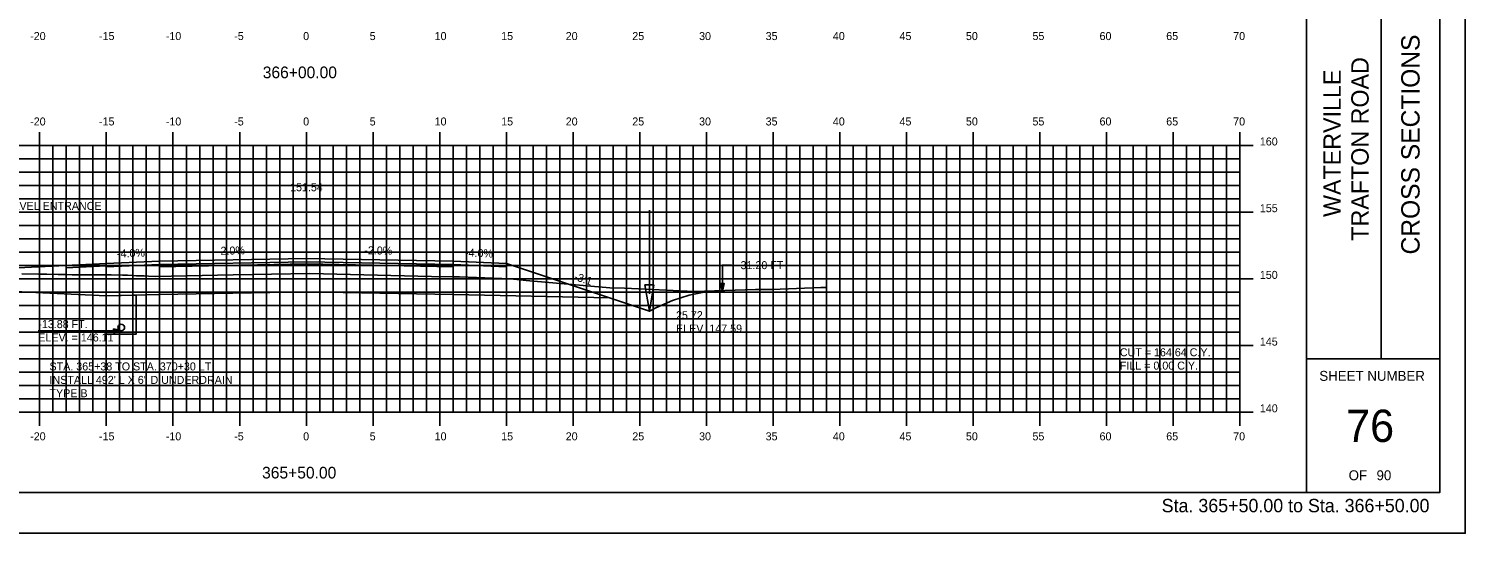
# Model space of a CAD drawing. Extents: x 1147412 to 1147582, y 608981 to 609091.
# Drawn here: x 1147473.9 to 1147581.6, y 608981.3 to 609019.1 of the extents above; entities that cross this region are included whole.
import ezdxf

# ---------------------------------------------------------------- set-up
doc = ezdxf.new("R2010")
doc.units = 0
for name, color, linetype in [('ANNOTATION', 7, 'Continuous'), ('BORDER', 7, 'Continuous'), ('D_Drainage_Ditch_Line', 7, 'Continuous'), ('D_Drainage_Underdrain', 7, 'Continuous'), ('D_Drainage_Underdrain_06in', 7, 'Continuous'), ('D_Roadway_Centerline', 7, 'Continuous'), ('D_Roadway_Centerline_Text', 7, 'Continuous'), ('D_Roadway_Edge_Shoulder', 7, 'Continuous'), ('D_Roadway_Edge_TW', 7, 'Continuous'), ('D_Roadway_Pavement', 7, 'Continuous'), ('D_Roadway_SlopeLines', 7, 'Continuous'), ('D_Roadway_SubGrade', 7, 'Continuous'), ('D_Text_Standard', 7, 'Continuous'), ('H_V ANNOTATION', 7, 'Continuous'), ('HIGHWAY_TITLE', 7, 'Continuous'), ('MAJOR', 7, 'Continuous'), ('MINOR', 7, 'Continuous'), ('PLOT BOUNDARY', 7, 'Continuous'), ('S_Roadway_Centerline', 7, 'Continuous')]:
    doc.layers.add(name, color=color, linetype=linetype)

msp = doc.modelspace()

# ---------------------------------------------------------------- linework, layer by layer
msp.add_lwpolyline([(1147464.92, 609000.76), (1147479.7, 609001.5), (1147483.7, 609001.66), (1147494.7, 609001.88), (1147505.7, 609001.66), (1147509.7, 609001.5), (1147517.42, 608998.92), (1147520.42, 608997.92), (1147520.9, 608998.16), (1147522.15, 608998.71), (1147523.4, 608999.11), (1147524.65, 608999.36), (1147525.9, 608999.46)])
at = {"layer": 'BORDER'}
for p, q in [((1147569.7, 608984.34), (1147569.7, 609089.34)), ((1147575.29, 608994.34), (1147575.29, 609029.34)), ((1147569.7, 608994.34), (1147579.7, 608994.34))]:
    msp.add_line(p, q, dxfattribs=at)
msp.add_lwpolyline([(1147419.7, 608984.34), (1147579.7, 608984.34), (1147579.7, 609089.34), (1147419.7, 609089.34)], close=True, dxfattribs=at)
at = {"layer": 'D_Drainage_Ditch_Line'}
msp.add_line((1147520.42, 608999.23), (1147520.42, 609005.48), dxfattribs=at)
msp.add_lwpolyline([(1147520.09, 608999.89), (1147520.75, 608999.89), (1147520.42, 608997.92)], close=True, dxfattribs=at)
at = {"layer": 'D_Drainage_Underdrain'}
msp.add_lwpolyline([(1147479.7, 608999.08), (1147479.7, 608996.2), (1147481.95, 608996.2), (1147481.95, 608999.12)], close=True, dxfattribs=at)
at = {"layer": 'D_Drainage_Underdrain_06in'}
msp.add_lwpolyline([(1147480.82, 608996.95), (1147480.9, 608996.93), (1147480.97, 608996.9), (1147481.02, 608996.84), (1147481.06, 608996.77), (1147481.07, 608996.7), (1147481.06, 608996.62), (1147481.02, 608996.55), (1147480.97, 608996.49), (1147480.9, 608996.46), (1147480.82, 608996.45), (1147480.75, 608996.46), (1147480.68, 608996.49), (1147480.62, 608996.55), (1147480.58, 608996.62), (1147480.57, 608996.7), (1147480.58, 608996.77), (1147480.62, 608996.84), (1147480.68, 608996.9), (1147480.75, 608996.93)], close=True, dxfattribs=at)
at = {"layer": 'D_Roadway_Edge_Shoulder'}
for points in [[(1147479.7, 609001.5), (1147476.7, 609001.35), (1147476.7, 609001.18), (1147479.7, 609001.33)], [(1147483.7, 609001.66), (1147479.7, 609001.5), (1147479.7, 609001.25), (1147483.7, 609001.41)], [(1147505.7, 609001.66), (1147509.7, 609001.5), (1147509.7, 609001.25), (1147505.7, 609001.41)]]:
    msp.add_lwpolyline(points, close=True, dxfattribs=at)
at = {"layer": 'D_Roadway_Edge_TW'}
msp.add_lwpolyline([(1147483.7, 609001.41), (1147483.7, 609001.66), (1147494.7, 609001.88), (1147505.7, 609001.66), (1147505.7, 609001.41), (1147494.7, 609001.63)], close=True, dxfattribs=at)
at = {"layer": 'D_Roadway_Pavement'}
msp.add_lwpolyline([(1147483.7, 609001.24), (1147483.7, 609001.41), (1147494.7, 609001.63), (1147505.7, 609001.41), (1147505.7, 609001.24), (1147494.7, 609001.46)], close=True, dxfattribs=at)
at = {"layer": 'D_Roadway_SlopeLines'}
for points in [[(1147520.42, 608997.92), (1147520.9, 608998.16), (1147522.15, 608998.71), (1147523.4, 608999.11), (1147524.65, 608999.36), (1147525.9, 608999.46)], [(1147517.42, 608998.92), (1147520.42, 608997.92)]]:
    msp.add_lwpolyline(points, dxfattribs=at)
at = {"layer": 'D_Roadway_SubGrade'}
for points in [[(1147464.92, 608999.76), (1147479.7, 608999.08), (1147483.7, 608999.16), (1147483.7, 609001.24), (1147483.7, 609001.41), (1147479.7, 609001.25), (1147479.7, 609001.5), (1147464.92, 609000.76)], [(1147483.7, 608999.16), (1147483.7, 609001.24), (1147494.7, 609001.46), (1147505.7, 609001.24), (1147505.7, 608999.16), (1147494.7, 608999.38)], [(1147505.7, 609001.24), (1147505.7, 609001.41), (1147509.7, 609001.25), (1147509.7, 609001.5), (1147509.7, 609001.5), (1147517.42, 608998.92), (1147505.7, 608999.16)]]:
    msp.add_lwpolyline(points, close=True, dxfattribs=at)
at = {"layer": 'D_Text_Standard'}
msp.add_line((1147474.6, 608996.45), (1147479.02, 608996.45), dxfattribs=at)
for points in [[(1147525.9, 608999.41), (1147525.9, 609001.37), (1147526.58, 609001.37)], [(1147480.82, 608996.45), (1147479.7, 608996.45), (1147479.02, 608996.45)]]:
    msp.add_lwpolyline(points, dxfattribs=at)
for points in [[(1147525.9, 608999.41), (1147525.75, 608999.99), (1147526.04, 608999.99)], [(1147480.82, 608996.45), (1147480.24, 608996.3), (1147480.24, 608996.59)]]:
    msp.add_lwpolyline(points, close=True, dxfattribs=at)
at = {"layer": 'MAJOR'}
for p, q in [((1147474.7, 609011.34), (1147474.7, 609010.34)), ((1147479.7, 609011.34), (1147479.7, 609010.34)), ((1147484.7, 609011.34), (1147484.7, 609010.34)), ((1147489.7, 609011.34), (1147489.7, 609010.34)), ((1147494.7, 609011.34), (1147494.7, 609010.34)), ((1147499.7, 609011.34), (1147499.7, 609010.34)), ((1147504.7, 609011.34), (1147504.7, 609010.34)), ((1147509.7, 609011.34), (1147509.7, 609010.34)), ((1147514.7, 609011.34), (1147514.7, 609010.34)), ((1147519.7, 609011.34), (1147519.7, 609010.34)), ((1147524.7, 609011.34), (1147524.7, 609010.34)), ((1147529.7, 609011.34), (1147529.7, 609010.34)), ((1147534.7, 609011.34), (1147534.7, 609010.34)), ((1147539.7, 609011.34), (1147539.7, 609010.34)), ((1147544.7, 609011.34), (1147544.7, 609010.34)), ((1147549.7, 609011.34), (1147549.7, 609010.34)), ((1147554.7, 609011.34), (1147554.7, 609010.34)), ((1147559.7, 609011.34), (1147559.7, 609010.34)), ((1147564.7, 609011.34), (1147564.7, 609010.34)), ((1147424.7, 609010.34), (1147564.7, 609010.34)), ((1147424.7, 609010.34), (1147564.7, 609010.34)), ((1147474.7, 608990.34), (1147474.7, 609010.34)), ((1147479.7, 608990.34), (1147479.7, 609010.34)), ((1147484.7, 608990.34), (1147484.7, 609010.34)), ((1147489.7, 608990.34), (1147489.7, 609010.34)), ((1147494.7, 608990.34), (1147494.7, 609010.34)), ((1147499.7, 608990.34), (1147499.7, 609010.34)), ((1147504.7, 608990.34), (1147504.7, 609010.34)), ((1147509.7, 608990.34), (1147509.7, 609010.34)), ((1147514.7, 608990.34), (1147514.7, 609010.34)), ((1147519.7, 608990.34), (1147519.7, 609010.34)), ((1147524.7, 608990.34), (1147524.7, 609010.34)), ((1147529.7, 608990.34), (1147529.7, 609010.34)), ((1147534.7, 608990.34), (1147534.7, 609010.34)), ((1147539.7, 608990.34), (1147539.7, 609010.34)), ((1147544.7, 608990.34), (1147544.7, 609010.34)), ((1147549.7, 608990.34), (1147549.7, 609010.34)), ((1147554.7, 608990.34), (1147554.7, 609010.34)), ((1147559.7, 608990.34), (1147559.7, 609010.34)), ((1147565.7, 609010.34), (1147563.7, 609010.34)), ((1147564.7, 608990.34), (1147564.7, 609010.34)), ((1147564.7, 608990.34), (1147564.7, 609010.34)), ((1147424.7, 609005.34), (1147564.7, 609005.34)), ((1147565.7, 609005.34), (1147563.7, 609005.34)), ((1147424.7, 609000.34), (1147564.7, 609000.34)), ((1147565.7, 609000.34), (1147563.7, 609000.34)), ((1147424.7, 608995.34), (1147564.7, 608995.34)), ((1147565.7, 608995.34), (1147563.7, 608995.34)), ((1147424.7, 608990.34), (1147564.7, 608990.34)), ((1147424.7, 608990.34), (1147564.7, 608990.34)), ((1147474.7, 608989.33), (1147474.7, 608990.34)), ((1147479.7, 608989.33), (1147479.7, 608990.34)), ((1147484.7, 608989.33), (1147484.7, 608990.34)), ((1147489.7, 608989.33), (1147489.7, 608990.34)), ((1147494.7, 608989.33), (1147494.7, 608990.34)), ((1147499.7, 608989.33), (1147499.7, 608990.34)), ((1147504.7, 608989.33), (1147504.7, 608990.34)), ((1147509.7, 608989.33), (1147509.7, 608990.34)), ((1147514.7, 608989.33), (1147514.7, 608990.34)), ((1147519.7, 608989.33), (1147519.7, 608990.34)), ((1147524.7, 608989.33), (1147524.7, 608990.34)), ((1147529.7, 608989.33), (1147529.7, 608990.34)), ((1147534.7, 608989.33), (1147534.7, 608990.34)), ((1147539.7, 608989.33), (1147539.7, 608990.34)), ((1147544.7, 608989.33), (1147544.7, 608990.34)), ((1147549.7, 608989.33), (1147549.7, 608990.34)), ((1147554.7, 608989.33), (1147554.7, 608990.34)), ((1147559.7, 608989.33), (1147559.7, 608990.34)), ((1147565.7, 608990.34), (1147563.7, 608990.34)), ((1147564.7, 608989.33), (1147564.7, 608990.34))]:
    msp.add_line(p, q, dxfattribs=at)
at = {"layer": 'MINOR'}
for p, q in [((1147475.7, 608990.34), (1147475.7, 609010.34)), ((1147476.7, 608990.34), (1147476.7, 609010.34)), ((1147477.7, 608990.34), (1147477.7, 609010.34)), ((1147478.7, 608990.34), (1147478.7, 609010.34)), ((1147480.7, 608990.34), (1147480.7, 609010.34)), ((1147481.7, 608990.34), (1147481.7, 609010.34)), ((1147482.7, 608990.34), (1147482.7, 609010.34)), ((1147483.7, 608990.34), (1147483.7, 609010.34)), ((1147485.7, 608990.34), (1147485.7, 609010.34)), ((1147486.7, 608990.34), (1147486.7, 609010.34)), ((1147487.7, 608990.34), (1147487.7, 609010.34)), ((1147488.7, 608990.34), (1147488.7, 609010.34)), ((1147490.7, 608990.34), (1147490.7, 609010.34)), ((1147491.7, 608990.34), (1147491.7, 609010.34)), ((1147492.7, 608990.34), (1147492.7, 609010.34)), ((1147493.7, 608990.34), (1147493.7, 609010.34)), ((1147495.7, 608990.34), (1147495.7, 609010.34)), ((1147496.7, 608990.34), (1147496.7, 609010.34)), ((1147497.7, 608990.34), (1147497.7, 609010.34)), ((1147498.7, 608990.34), (1147498.7, 609010.34)), ((1147500.7, 608990.34), (1147500.7, 609010.34)), ((1147501.7, 608990.34), (1147501.7, 609010.34)), ((1147502.7, 608990.34), (1147502.7, 609010.34)), ((1147503.7, 608990.34), (1147503.7, 609010.34)), ((1147505.7, 608990.34), (1147505.7, 609010.34)), ((1147506.7, 608990.34), (1147506.7, 609010.34)), ((1147507.7, 608990.34), (1147507.7, 609010.34)), ((1147508.7, 608990.34), (1147508.7, 609010.34)), ((1147510.7, 608990.34), (1147510.7, 609010.34)), ((1147511.7, 608990.34), (1147511.7, 609010.34)), ((1147512.7, 608990.34), (1147512.7, 609010.34)), ((1147513.7, 608990.34), (1147513.7, 609010.34)), ((1147515.7, 608990.34), (1147515.7, 609010.34)), ((1147516.7, 608990.34), (1147516.7, 609010.34)), ((1147517.7, 608990.34), (1147517.7, 609010.34)), ((1147518.7, 608990.34), (1147518.7, 609010.34)), ((1147520.7, 608990.34), (1147520.7, 609010.34)), ((1147521.7, 608990.34), (1147521.7, 609010.34)), ((1147522.7, 608990.34), (1147522.7, 609010.34)), ((1147523.7, 608990.34), (1147523.7, 609010.34)), ((1147525.7, 608990.34), (1147525.7, 609010.34)), ((1147526.7, 608990.34), (1147526.7, 609010.34)), ((1147527.7, 608990.34), (1147527.7, 609010.34)), ((1147528.7, 608990.34), (1147528.7, 609010.34)), ((1147530.7, 608990.34), (1147530.7, 609010.34)), ((1147531.7, 608990.34), (1147531.7, 609010.34)), ((1147532.7, 608990.34), (1147532.7, 609010.34)), ((1147533.7, 608990.34), (1147533.7, 609010.34)), ((1147535.7, 608990.34), (1147535.7, 609010.34)), ((1147536.7, 608990.34), (1147536.7, 609010.34)), ((1147537.7, 608990.34), (1147537.7, 609010.34)), ((1147538.7, 608990.34), (1147538.7, 609010.34)), ((1147540.7, 608990.34), (1147540.7, 609010.34)), ((1147541.7, 608990.34), (1147541.7, 609010.34)), ((1147542.7, 608990.34), (1147542.7, 609010.34)), ((1147543.7, 608990.34), (1147543.7, 609010.34)), ((1147545.7, 608990.34), (1147545.7, 609010.34)), ((1147546.7, 608990.34), (1147546.7, 609010.34)), ((1147547.7, 608990.34), (1147547.7, 609010.34)), ((1147548.7, 608990.34), (1147548.7, 609010.34)), ((1147550.7, 608990.34), (1147550.7, 609010.34)), ((1147551.7, 608990.34), (1147551.7, 609010.34)), ((1147552.7, 608990.34), (1147552.7, 609010.34)), ((1147553.7, 608990.34), (1147553.7, 609010.34)), ((1147555.7, 608990.34), (1147555.7, 609010.34)), ((1147556.7, 608990.34), (1147556.7, 609010.34)), ((1147557.7, 608990.34), (1147557.7, 609010.34)), ((1147558.7, 608990.34), (1147558.7, 609010.34)), ((1147560.7, 608990.34), (1147560.7, 609010.34)), ((1147561.7, 608990.34), (1147561.7, 609010.34)), ((1147562.7, 608990.34), (1147562.7, 609010.34)), ((1147563.7, 608990.34), (1147563.7, 609010.34)), ((1147424.7, 609009.34), (1147564.7, 609009.34)), ((1147564.7, 609009.34), (1147563.7, 609009.34)), ((1147424.7, 609008.34), (1147564.7, 609008.34)), ((1147564.7, 609008.34), (1147563.7, 609008.34)), ((1147424.7, 609007.34), (1147564.7, 609007.34)), ((1147564.7, 609007.34), (1147563.7, 609007.34)), ((1147424.7, 609006.34), (1147564.7, 609006.34)), ((1147564.7, 609006.34), (1147563.7, 609006.34)), ((1147424.7, 609004.34), (1147564.7, 609004.34)), ((1147564.7, 609004.34), (1147563.7, 609004.34)), ((1147424.7, 609003.34), (1147564.7, 609003.34)), ((1147564.7, 609003.34), (1147563.7, 609003.34)), ((1147424.7, 609002.34), (1147564.7, 609002.34)), ((1147424.7, 609001.34), (1147564.7, 609001.34)), ((1147564.7, 609002.34), (1147563.7, 609002.34)), ((1147564.7, 609001.34), (1147563.7, 609001.34)), ((1147424.7, 608999.34), (1147564.7, 608999.34)), ((1147564.7, 608999.34), (1147563.7, 608999.34)), ((1147424.7, 608998.34), (1147564.7, 608998.34)), ((1147564.7, 608998.34), (1147563.7, 608998.34)), ((1147424.7, 608997.34), (1147564.7, 608997.34)), ((1147564.7, 608997.34), (1147563.7, 608997.34)), ((1147424.7, 608996.34), (1147564.7, 608996.34)), ((1147564.7, 608996.34), (1147563.7, 608996.34)), ((1147424.7, 608994.34), (1147564.7, 608994.34)), ((1147564.7, 608994.34), (1147563.7, 608994.34)), ((1147424.7, 608993.34), (1147564.7, 608993.34)), ((1147564.7, 608993.34), (1147563.7, 608993.34)), ((1147424.7, 608992.34), (1147564.7, 608992.34)), ((1147564.7, 608992.34), (1147563.7, 608992.34)), ((1147424.7, 608991.34), (1147564.7, 608991.34)), ((1147564.7, 608991.34), (1147563.7, 608991.34))]:
    msp.add_line(p, q, dxfattribs=at)
at = {"layer": 'PLOT BOUNDARY'}
msp.add_lwpolyline([(1147411.6, 608981.28), (1147581.6, 608981.28), (1147581.6, 609091.28), (1147411.6, 609091.28)], close=True, dxfattribs=at)
at = {"layer": 'S_Roadway_Centerline'}
msp.add_lwpolyline([(1147473.36, 609000.72), (1147474.62, 609000.7), (1147475.23, 609000.69), (1147476.09, 609000.68), (1147476.74, 609000.66), (1147477.14, 609000.65), (1147480.07, 609000.64), (1147480.91, 609000.62), (1147481.29, 609000.61), (1147481.96, 609000.58), (1147482.53, 609000.56), (1147482.86, 609000.55), (1147483.4, 609000.52), (1147489.22, 609000.64), (1147494.95, 609000.74), (1147504.08, 609000.52), (1147505.68, 609000.5), (1147506.19, 609000.49), (1147510.01, 609000.35), (1147511.19, 609000.22), (1147517.46, 608999.68), (1147518.55, 608999.64), (1147523.78, 608999.39), (1147528.39, 608999.54), (1147529.62, 608999.54), (1147533.29, 608999.7), (1147533.67, 608999.7)], dxfattribs=at)

# ---------------------------------------------------------------- texts
at = {"layer": 'ANNOTATION'}
for s, p in [('CONSTRUCT GRAVEL ENTRANCE', (1147466.19, 609005.51)), ('STA. 365+38 TO STA. 370+30 LT', (1147475.44, 608993.48)), ('INSTALL 492\' L X 6" D UNDERDRAIN', (1147475.44, 608992.47)), ('TYPE B', (1147475.44, 608991.47))]:
    msp.add_text(s, height=0.6, dxfattribs=at).set_placement(p)
for s, rotation, p in [('-4.0%', 2.2906, (1147480.51, 609001.93)), ('-2.0%', 1.1458, (1147488, 609002.14)), ('-2.0%', 358.8542, (1147499.04, 609002.19)), ('-4.0%', 357.7094, (1147506.59, 609002.02)), ('-3:1', 341.5652, (1147514.71, 609000.28))]:
    msp.add_text(s, height=0.6, rotation=rotation, dxfattribs=at).set_placement(p)
at = {"layer": 'BORDER'}
msp.add_text('CROSS SECTIONS', height=1.3779, rotation=90, dxfattribs=at).set_placement((1147578.18, 609002.17))
for s, height, p in [('SHEET NUMBER', 0.7453, (1147570.66, 608992.7)), ('76', 2.419, (1147572.67, 608988.12)), ('OF', 0.745, (1147572.86, 608985.25)), ('90', 0.745, (1147574.95, 608985.25))]:
    msp.add_text(s, height=height, dxfattribs=at).set_placement(p)
at = {"layer": 'D_Roadway_Centerline'}
for s, p in [('C', (1147494.69, 609001.88)), ('L', (1147494.7, 609001.87))]:
    msp.add_text(s, height=0.0146, dxfattribs=at).set_placement(p)
at = {"layer": 'D_Roadway_Centerline_Text'}
msp.add_text('151.54', height=0.6, dxfattribs=at).set_placement((1147493.48, 609006.91))
at = {"layer": 'D_Text_Standard'}
for s, p in [('31.20 FT', (1147527.26, 609001.07)), ('-13.88 FT.', (1147474.6, 608996.65)), ('25.72', (1147522.42, 608997.32)), ('ELEV. = 146.11', (1147474.6, 608995.65)), ('ELEV. 147.59', (1147522.42, 608996.32)), ('CUT = 164.64 C.Y.', (1147555.7, 608994.54)), ('FILL = 0.00 C.Y.', (1147555.7, 608993.54))]:
    msp.add_text(s, height=0.6, dxfattribs=at).set_placement(p)
at = {"layer": 'H_V ANNOTATION'}
for s, height, p in [('-20', 0.6, (1147473.99, 609018.24)), ('-15', 0.6, (1147479.15, 609018.24)), ('-10', 0.6, (1147484.16, 609018.24)), ('-5', 0.6, (1147489.29, 609018.24)), ('0', 0.6, (1147494.46, 609018.24)), ('5', 0.6, (1147499.45, 609018.24)), ('10', 0.6, (1147504.32, 609018.24)), ('15', 0.6, (1147509.31, 609018.24)), ('20', 0.6, (1147514.15, 609018.24)), ('25', 0.6, (1147519.14, 609018.24)), ('30', 0.6, (1147524.15, 609018.24)), ('35', 0.6, (1147529.14, 609018.24)), ('40', 0.6, (1147534.18, 609018.24)), ('45', 0.6, (1147539.18, 609018.24)), ('50', 0.6, (1147544.16, 609018.24)), ('55', 0.6, (1147549.15, 609018.24)), ('60', 0.6, (1147554.18, 609018.24)), ('65', 0.6, (1147559.18, 609018.24)), ('70', 0.6, (1147564.2, 609018.24)), ('366+00.00', 0.875, (1147491.43, 609015.38)), ('-20', 0.6, (1147473.99, 609011.84)), ('-15', 0.6, (1147479.15, 609011.84)), ('-10', 0.6, (1147484.16, 609011.84)), ('-5', 0.6, (1147489.29, 609011.84)), ('0', 0.6, (1147494.46, 609011.84)), ('5', 0.6, (1147499.45, 609011.84)), ('10', 0.6, (1147504.32, 609011.84)), ('15', 0.6, (1147509.31, 609011.84)), ('20', 0.6, (1147514.15, 609011.84)), ('25', 0.6, (1147519.14, 609011.84)), ('30', 0.6, (1147524.15, 609011.84)), ('35', 0.6, (1147529.14, 609011.84)), ('40', 0.6, (1147534.18, 609011.84)), ('45', 0.6, (1147539.18, 609011.84)), ('50', 0.6, (1147544.16, 609011.84)), ('55', 0.6, (1147549.15, 609011.84)), ('60', 0.6, (1147554.18, 609011.84)), ('65', 0.6, (1147559.18, 609011.84)), ('70', 0.6, (1147564.2, 609011.84)), ('160', 0.6, (1147566.2, 609010.34)), ('155', 0.6, (1147566.2, 609005.34)), ('150', 0.6, (1147566.2, 609000.34)), ('145', 0.6, (1147566.2, 608995.34)), ('140', 0.6, (1147566.2, 608990.34)), ('-20', 0.6, (1147473.99, 608988.24)), ('-15', 0.6, (1147479.15, 608988.24)), ('-10', 0.6, (1147484.16, 608988.24)), ('-5', 0.6, (1147489.29, 608988.24)), ('0', 0.6, (1147494.46, 608988.24)), ('5', 0.6, (1147499.45, 608988.24)), ('10', 0.6, (1147504.32, 608988.24)), ('15', 0.6, (1147509.31, 608988.24)), ('20', 0.6, (1147514.15, 608988.24)), ('25', 0.6, (1147519.14, 608988.24)), ('30', 0.6, (1147524.15, 608988.24)), ('35', 0.6, (1147529.14, 608988.24)), ('40', 0.6, (1147534.18, 608988.24)), ('45', 0.6, (1147539.18, 608988.24)), ('50', 0.6, (1147544.16, 608988.24)), ('55', 0.6, (1147549.15, 608988.24)), ('60', 0.6, (1147554.18, 608988.24)), ('65', 0.6, (1147559.18, 608988.24)), ('70', 0.6, (1147564.2, 608988.24)), ('365+50.00', 0.875, (1147491.38, 608985.38)), ('Sta. 365+50.00 to Sta. 366+50.00', 1.0002, (1147558.84, 608982.85))]:
    msp.add_text(s, height=height, dxfattribs=at).set_placement(p)
at = {"layer": 'HIGHWAY_TITLE'}
for s, height, p in [('TRAFTON ROAD', 1.3043, (1147574.36, 609003.2)), ('WATERVILLE', 1.304, (1147572.27, 609004.98))]:
    msp.add_text(s, height=height, rotation=90, dxfattribs=at).set_placement(p)
at = {"layer": 'S_Roadway_Centerline'}
for s, p in [('C', (1147494.94, 609000.74)), ('L', (1147494.95, 609000.73))]:
    msp.add_text(s, height=0.0146, dxfattribs=at).set_placement(p)

doc.saveas('drawing.dxf')
